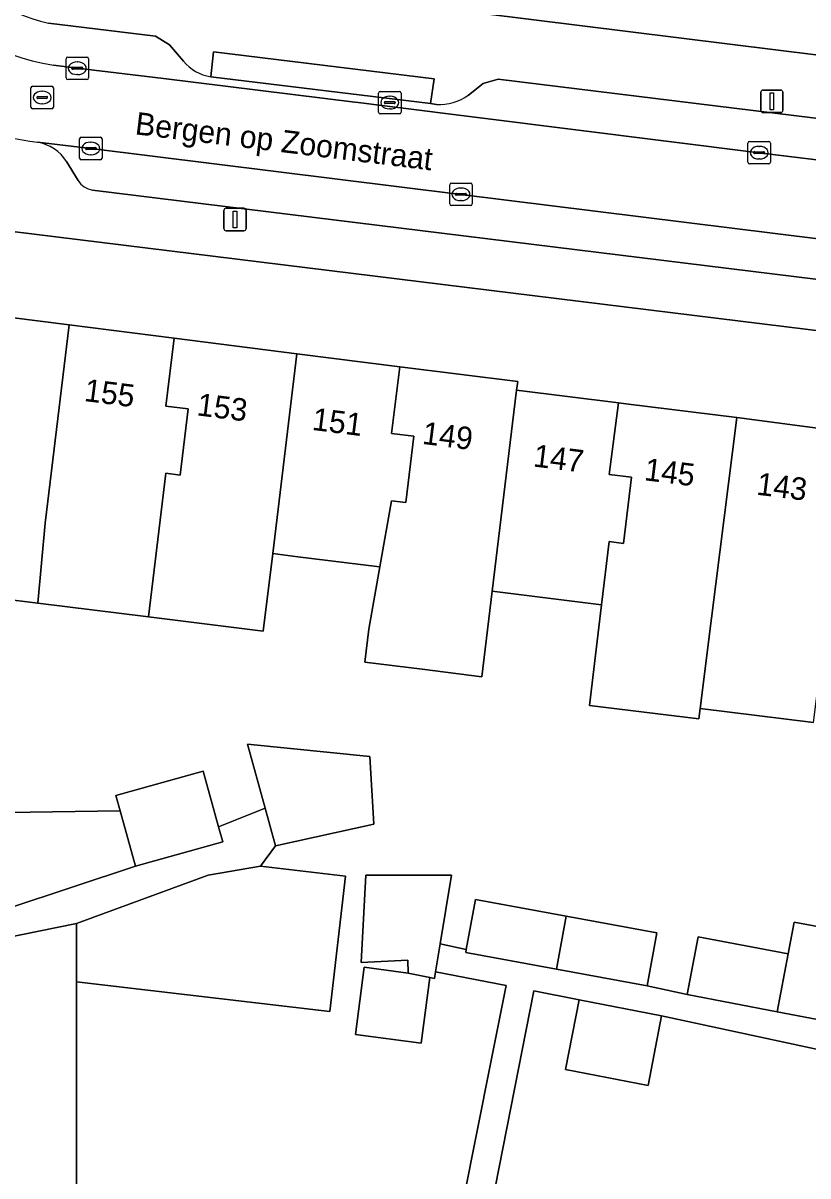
# Model space of a CAD drawing. Extents: x 158086 to 159499, y 382904 to 383981.
# Drawn here: x 158153 to 158187.9, y 383245.1 to 383296.4 of the extents above; entities that cross this region are included whole.
import ezdxf

# ---------------------------------------------------------------- set-up
doc = ezdxf.new("R2010")
doc.units = 0
for name, color, linetype in [('IMGEO_Erf', 7, 'Continuous'), ('IMGEO_Kolk', 7, 'Continuous'), ('IMGEO_Lichtmast', 7, 'Continuous'), ('IMGEO_Openbare_ruimte_label', 7, 'Continuous'), ('IMGEO_Pand', 7, 'Continuous'), ('IMGEO_Pand_nummerreeks', 7, 'Continuous'), ('IMGEO_Parkeervlak_open', 7, 'Continuous'), ('IMGEO_Rijbaan_lokaal_open', 7, 'Continuous'), ('IMGEO_Rioolput', 7, 'Continuous'), ('IMGEO_Voetpad_open', 7, 'Continuous')]:
    doc.layers.add(name, color=color, linetype=linetype)

msp = doc.modelspace()

# ---------------------------------------------------------------- linework, layer by layer
at = {"layer": 'IMGEO_Erf'}
for points in [[(158209.755, 383315.214), (158208.52, 383315.331), (158208.189, 383312.446), (158204.345, 383312.887), (158204.46, 383313.889), (158201.32, 383314.249), (158201.561, 383316.349), (158199.529, 383316.599), (158199.3, 383314.601), (158195.034, 383311.729), (158193.798, 383313.563), (158180.21, 383304.272), (158180.21, 383303.461), (158171.168, 383297.074), (158186.591, 383295.165), (158240.182, 383288.537)], [(158188.163, 383265.252), (158183.107, 383265.876), (158183.05, 383265.426), (158178.18, 383266.016), (158178.722, 383270.493), (158173.853, 383271.094), (158173.391, 383267.293), (158170.741, 383267.624), (158168.187, 383267.943), (158168.371, 383269.412), (158168.857, 383272.174), (158168.719, 383272.191), (158165.209, 383272.63), (158164.088, 383272.77), (158163.663, 383269.323), (158158.563, 383269.952), (158153.625, 383270.561), (158148.582, 383271.182)], [(158152.279, 383261.248), (158157.29, 383261.32), (158157.099, 383262.004), (158160.989, 383263.089), (158161.678, 383260.617), (158163.75, 383261.445), (158162.957, 383264.29), (158168.411, 383263.741), (158168.593, 383260.732), (158164.215, 383259.776), (158163.541, 383258.86), (158167.324, 383258.421), (158166.626, 383252.405), (158155.348, 383253.712), (158155.352, 383242.078)], [(158171.948, 383240.905), (158173.795, 383250.149), (158174.473, 383253.551), (158171.329, 383254.171), (158171.28, 383253.873), (158171.074, 383253.915), (158170.699, 383250.993), (158167.766, 383251.37), (158168.151, 383254.364), (158170.117, 383254.111), (158170.098, 383254.684), (158168.023, 383254.585), (158168.232, 383258.465), (158172.042, 383258.471), (158171.534, 383255.403), (158172.699, 383255.158), (158173.106, 383257.383), (158177.143, 383256.644), (158181.18, 383255.905), (158180.748, 383253.547), (158182.537, 383253.154), (158183.024, 383255.723), (158187.034, 383254.963), (158187.302, 383256.377), (158191.272, 383255.625)], [(158199.077, 383244.67), (158199.655, 383247.658), (158197.155, 383248.138), (158196.461, 383245.085), (158192.336, 383246.023), (158193.03, 383249.076), (158193.162, 383249.657), (158188.003, 383250.786), (158181.398, 383252.206), (158180.792, 383249.102), (158177.118, 383249.82), (158177.725, 383252.924), (158175.714, 383253.312), (158172.957, 383239.361)]]:
    msp.add_lwpolyline(points, dxfattribs=at)
msp.add_lwpolyline([(158145.267, 383287.982), (158144.807, 383284.241), (158149.73, 383283.618), (158155.024, 383282.947), (158159.702, 383282.355), (158165.165, 383281.663), (158169.74, 383281.084), (158174.989, 383280.42), (158174.941, 383280.041), (158179.471, 383279.48), (158179.804, 383279.439), (158184.749, 383278.826), (158189.344, 383278.218), (158189.698, 383278.214), (158194.749, 383277.588), (158199.264, 383277.029), (158199.607, 383276.987), (158204.62, 383276.366), (158205.148, 383280.625)], close=True, dxfattribs=at)
at = {"layer": 'IMGEO_Kolk'}
for p, q in [((158154.961, 383294.861), (158155.813, 383294.861)), ((158154.886, 383293.935), (158154.886, 383294.787)), ((158155.145, 383294.355), (158155.145, 383294.367)), ((158155.188, 383294.404), (158155.586, 383294.404)), ((158155.374, 383294.641), (158155.399, 383294.641)), ((158155.629, 383294.367), (158155.629, 383294.355)), ((158155.887, 383294.787), (158155.887, 383293.935)), ((158155.813, 383293.861), (158154.961, 383293.861)), ((158155.583, 383294.318), (158155.185, 383294.318)), ((158155.397, 383294.081), (158155.372, 383294.081)), ((158168.871, 383293.333), (158169.723, 383293.333)), ((158168.796, 383292.407), (158168.796, 383293.259)), ((158169.055, 383292.827), (158169.055, 383292.839)), ((158169.098, 383292.876), (158169.496, 383292.876)), ((158169.284, 383293.113), (158169.309, 383293.113)), ((158169.539, 383292.839), (158169.539, 383292.827)), ((158169.797, 383293.259), (158169.797, 383292.407)), ((158169.723, 383292.333), (158168.871, 383292.333)), ((158169.493, 383292.79), (158169.095, 383292.79)), ((158169.307, 383292.553), (158169.282, 383292.553)), ((158155.564, 383291.293), (158156.416, 383291.293)), ((158155.489, 383290.367), (158155.489, 383291.219)), ((158155.748, 383290.787), (158155.748, 383290.799)), ((158155.791, 383290.836), (158156.189, 383290.836)), ((158155.977, 383291.073), (158156.002, 383291.073)), ((158156.232, 383290.799), (158156.232, 383290.787)), ((158156.49, 383291.219), (158156.49, 383290.367)), ((158185.239, 383290.18), (158185.239, 383291.032)), ((158185.314, 383291.106), (158186.166, 383291.106)), ((158185.727, 383290.886), (158185.752, 383290.886)), ((158186.24, 383291.032), (158186.24, 383290.18)), ((158156.416, 383290.293), (158155.564, 383290.293)), ((158156.186, 383290.75), (158155.788, 383290.75)), ((158156, 383290.513), (158155.975, 383290.513)), ((158185.498, 383290.6), (158185.498, 383290.612)), ((158185.936, 383290.563), (158185.538, 383290.563)), ((158185.541, 383290.649), (158185.939, 383290.649)), ((158185.75, 383290.326), (158185.725, 383290.326)), ((158185.982, 383290.612), (158185.982, 383290.6)), ((158186.166, 383290.106), (158185.314, 383290.106)), ((158172.04, 383289.251), (158172.892, 383289.251)), ((158171.965, 383288.325), (158171.965, 383289.177)), ((158172.224, 383288.745), (158172.224, 383288.757)), ((158172.662, 383288.708), (158172.264, 383288.708)), ((158172.267, 383288.794), (158172.665, 383288.794)), ((158172.453, 383289.031), (158172.478, 383289.031)), ((158172.708, 383288.757), (158172.708, 383288.745)), ((158172.966, 383289.177), (158172.966, 383288.325)), ((158172.892, 383288.251), (158172.04, 383288.251)), ((158172.476, 383288.471), (158172.451, 383288.471))]:
    msp.add_line(p, q, dxfattribs=at)
for points in [[(158154.961, 383294.861), (158155.813, 383294.861)], [(158154.886, 383293.935), (158154.886, 383294.787)], [(158155.887, 383294.787), (158155.887, 383293.935)], [(158155.813, 383293.861), (158154.961, 383293.861)], [(158168.871, 383293.333), (158169.723, 383293.333)], [(158168.796, 383292.407), (158168.796, 383293.259)], [(158169.797, 383293.259), (158169.797, 383292.407)], [(158169.723, 383292.333), (158168.871, 383292.333)], [(158155.564, 383291.293), (158156.416, 383291.293)], [(158155.489, 383290.367), (158155.489, 383291.219)], [(158156.49, 383291.219), (158156.49, 383290.367)], [(158185.239, 383290.18), (158185.239, 383291.032)], [(158185.314, 383291.106), (158186.166, 383291.106)], [(158186.24, 383291.032), (158186.24, 383290.18)], [(158156.416, 383290.293), (158155.564, 383290.293)], [(158186.166, 383290.106), (158185.314, 383290.106)], [(158172.04, 383289.251), (158172.892, 383289.251)], [(158171.965, 383288.325), (158171.965, 383289.177)], [(158172.966, 383289.177), (158172.966, 383288.325)], [(158172.892, 383288.251), (158172.04, 383288.251)]]:
    msp.add_lwpolyline(points, dxfattribs=at)
for centre, radius, start, end in [((158154.963, 383294.785), 0.0765, 91.552, 178.448), ((158154.963, 383294.785), 0.0765, 91.552, 178.448), ((158155.811, 383294.785), 0.0765, 1.552, 88.448), ((158155.811, 383294.785), 0.0765, 1.552, 88.448), ((158155.185, 383294.364), 0.0403, 85.8775, 175.7526), ((158155.182, 383294.354), 0.0366, 178.938, 274.7102), ((158155.586, 383294.361), 0.043, 264.8664, 352.4533), ((158155.59, 383294.366), 0.0386, 1.7309, 96.639), ((158154.963, 383293.937), 0.0765, 181.552, 268.448), ((158154.963, 383293.937), 0.0765, 181.552, 268.448), ((158155.811, 383293.937), 0.0765, 271.552, 358.448), ((158155.811, 383293.937), 0.0765, 271.552, 358.448), ((158168.873, 383293.257), 0.0765, 91.552, 178.448), ((158168.873, 383293.257), 0.0765, 91.552, 178.448), ((158169.721, 383293.257), 0.0765, 1.552, 88.448), ((158169.721, 383293.257), 0.0765, 1.552, 88.448), ((158169.095, 383292.836), 0.0403, 85.8775, 175.7526), ((158169.092, 383292.826), 0.0366, 178.938, 274.7102), ((158169.496, 383292.833), 0.043, 264.8664, 352.4533), ((158169.5, 383292.838), 0.0386, 1.7309, 96.639), ((158168.873, 383292.409), 0.0765, 181.552, 268.448), ((158168.873, 383292.409), 0.0765, 181.552, 268.448), ((158169.721, 383292.409), 0.0765, 271.552, 358.448), ((158169.721, 383292.409), 0.0765, 271.552, 358.448), ((158155.566, 383291.217), 0.0765, 91.552, 178.448), ((158155.566, 383291.217), 0.0765, 91.552, 178.448), ((158156.414, 383291.217), 0.0765, 1.552, 88.448), ((158156.414, 383291.217), 0.0765, 1.552, 88.448), ((158155.788, 383290.796), 0.0403, 85.8775, 175.7526), ((158155.785, 383290.786), 0.0366, 178.938, 274.7102), ((158156.189, 383290.793), 0.043, 264.8664, 352.4533), ((158156.193, 383290.798), 0.0386, 1.7309, 96.639), ((158185.316, 383291.03), 0.0765, 91.552, 178.448), ((158185.316, 383291.03), 0.0765, 91.552, 178.448), ((158186.164, 383291.03), 0.0765, 1.552, 88.448), ((158186.164, 383291.03), 0.0765, 1.552, 88.448), ((158155.566, 383290.369), 0.0765, 181.552, 268.448), ((158155.566, 383290.369), 0.0765, 181.552, 268.448), ((158156.414, 383290.369), 0.0765, 271.552, 358.448), ((158156.414, 383290.369), 0.0765, 271.552, 358.448), ((158185.538, 383290.609), 0.0403, 85.8775, 175.7526), ((158185.535, 383290.599), 0.0366, 178.938, 274.7102), ((158185.939, 383290.606), 0.043, 264.8664, 352.4533), ((158185.943, 383290.611), 0.0386, 1.7309, 96.639), ((158185.316, 383290.182), 0.0765, 181.552, 268.448), ((158185.316, 383290.182), 0.0765, 181.552, 268.448), ((158186.164, 383290.182), 0.0765, 271.552, 358.448), ((158186.164, 383290.182), 0.0765, 271.552, 358.448), ((158172.042, 383289.175), 0.0765, 91.552, 178.448), ((158172.042, 383289.175), 0.0765, 91.552, 178.448), ((158172.89, 383289.175), 0.0765, 1.552, 88.448), ((158172.89, 383289.175), 0.0765, 1.552, 88.448), ((158172.264, 383288.754), 0.0403, 85.8775, 175.7526), ((158172.261, 383288.744), 0.0366, 178.938, 274.7102), ((158172.665, 383288.751), 0.043, 264.8664, 352.4533), ((158172.669, 383288.756), 0.0386, 1.7309, 96.639), ((158172.042, 383288.327), 0.0765, 181.552, 268.448), ((158172.042, 383288.327), 0.0765, 181.552, 268.448), ((158172.89, 383288.327), 0.0765, 271.552, 358.448), ((158172.89, 383288.327), 0.0765, 271.552, 358.448)]:
    msp.add_arc(centre, radius, start, end, dxfattribs=at)
for centre, major_axis, ratio, start_param, end_param in [((158155.373, 383294.361), (-0.387, 0.002), 0.722429, 4.712389, 7.853982), ((158155.398, 383294.361), (-0.39, 0.002), 0.717154, 1.570796, 4.712389), ((158169.283, 383292.833), (-0.387, 0.002), 0.722429, 4.712389, 7.853982), ((158169.308, 383292.833), (-0.39, 0.002), 0.717154, 1.570796, 4.712389), ((158155.976, 383290.793), (-0.387, 0.002), 0.722429, 4.712389, 7.853982), ((158156.001, 383290.793), (-0.39, 0.002), 0.717154, 1.570796, 4.712389), ((158185.726, 383290.606), (-0.387, 0.002), 0.722429, 4.712389, 7.853982), ((158185.751, 383290.606), (-0.39, 0.002), 0.717154, 1.570796, 4.712389), ((158172.452, 383288.751), (-0.387, 0.002), 0.722429, 4.712389, 7.853982), ((158172.477, 383288.751), (-0.39, 0.002), 0.717154, 1.570796, 4.712389)]:
    msp.add_ellipse(centre, major_axis=major_axis, ratio=ratio, start_param=start_param, end_param=end_param, dxfattribs=at)
at = {"layer": 'IMGEO_Lichtmast'}
for p, q in [((158185.906, 383293.392), (158186.696, 383293.392)), ((158186.696, 383293.392), (158185.906, 383293.392)), ((158185.806, 383292.492), (158185.806, 383293.292)), ((158185.806, 383293.292), (158185.806, 383292.492)), ((158186.796, 383293.292), (158186.796, 383292.492)), ((158186.796, 383292.492), (158186.796, 383293.292)), ((158186.696, 383292.392), (158185.906, 383292.392)), ((158185.906, 383292.392), (158186.696, 383292.392)), ((158161.912, 383287.234), (158161.912, 383288.034)), ((158161.912, 383288.034), (158161.912, 383287.234)), ((158162.012, 383288.134), (158162.802, 383288.134)), ((158162.802, 383288.134), (158162.012, 383288.134)), ((158162.902, 383288.034), (158162.902, 383287.234)), ((158162.902, 383287.234), (158162.902, 383288.034)), ((158162.802, 383287.134), (158162.012, 383287.134)), ((158162.012, 383287.134), (158162.802, 383287.134))]:
    msp.add_line(p, q, dxfattribs=at)
for points in [[(158186.226, 383293.267), (158186.376, 383293.267), (158186.376, 383292.517), (158186.226, 383292.517), (158186.226, 383293.267)], [(158162.332, 383288.009), (158162.482, 383288.009), (158162.482, 383287.259), (158162.332, 383287.259), (158162.332, 383288.009)]]:
    msp.add_lwpolyline(points, dxfattribs=at)
for centre, start, end in [((158185.906, 383293.292), 90, 180), ((158185.906, 383293.292), 90, 180), ((158186.696, 383293.292), 0, 90), ((158186.696, 383293.292), 360, 90), ((158185.906, 383292.492), 180, 270), ((158185.906, 383292.492), 180, 270), ((158186.696, 383292.492), 270, 0), ((158186.696, 383292.492), 270, 0), ((158162.012, 383288.034), 90, 180), ((158162.012, 383288.034), 90, 180), ((158162.802, 383288.034), 0, 90), ((158162.802, 383288.034), 360, 90), ((158162.012, 383287.234), 180, 270), ((158162.012, 383287.234), 180, 270), ((158162.802, 383287.234), 270, 0), ((158162.802, 383287.234), 270, 0)]:
    msp.add_arc(centre, 0.1, start, end, dxfattribs=at)
at = {"layer": 'IMGEO_Pand'}
for points in [[(158149.73, 383283.618), (158149.364, 383280.593), (158150.356, 383280.472), (158150, 383277.528), (158149.36, 383277.606), (158148.582, 383271.182), (158153.625, 383270.561), (158153.955, 383274.12), (158155.024, 383282.947)], [(158158.563, 383269.952), (158159.33, 383276.341), (158159.97, 383276.263), (158160.326, 383279.207), (158159.334, 383279.328), (158159.702, 383282.355), (158155.024, 383282.947), (158153.955, 383274.12), (158153.625, 383270.561)], [(158158.563, 383269.952), (158163.663, 383269.323), (158164.088, 383272.77), (158165.165, 383281.663), (158159.702, 383282.355), (158159.334, 383279.328), (158160.326, 383279.207), (158159.97, 383276.263), (158159.33, 383276.341)], [(158169.74, 383281.084), (158165.165, 383281.663), (158164.088, 383272.77), (158165.209, 383272.63), (158168.719, 383272.191), (158168.857, 383272.174), (158169.376, 383275.124), (158170.016, 383275.046), (158170.372, 383277.99), (158169.38, 383278.111)], [(158174.941, 383280.041), (158174.989, 383280.42), (158169.74, 383281.084), (158169.38, 383278.111), (158170.372, 383277.99), (158170.016, 383275.046), (158169.376, 383275.124), (158168.857, 383272.174), (158168.371, 383269.412), (158168.187, 383267.943), (158170.741, 383267.624), (158173.391, 383267.293), (158173.853, 383271.094)], [(158180.058, 383276.17), (158179.066, 383276.291), (158179.471, 383279.48), (158174.941, 383280.041), (158173.853, 383271.094), (158178.722, 383270.493), (158179.062, 383273.304), (158179.702, 383273.226)], [(158184.749, 383278.826), (158179.804, 383279.439), (158179.471, 383279.48), (158179.066, 383276.291), (158180.058, 383276.17), (158179.702, 383273.226), (158179.062, 383273.304), (158178.722, 383270.493), (158178.18, 383266.016), (158183.05, 383265.426), (158183.107, 383265.876), (158183.616, 383269.89)], [(158189.344, 383278.218), (158184.749, 383278.826), (158183.616, 383269.89), (158183.107, 383265.876), (158188.163, 383265.252), (158188.658, 383269.268), (158188.958, 383272.1), (158189.598, 383272.022), (158189.954, 383274.966), (158188.962, 383275.087)], [(158163.75, 383261.445), (158164.215, 383259.776), (158168.593, 383260.732), (158168.411, 383263.741), (158162.957, 383264.29)], [(158157.29, 383261.32), (158157.976, 383258.86), (158161.866, 383259.944), (158161.678, 383260.617), (158160.989, 383263.089), (158157.099, 383262.004)], [(158157.29, 383261.32), (158152.279, 383261.248), (158152.296, 383260.053), (158152.336, 383257.26), (158152.34, 383256.989), (158157.976, 383258.86)], [(158163.541, 383258.86), (158161.21, 383258.471), (158155.347, 383256.316), (158155.348, 383253.712), (158166.626, 383252.405), (158167.324, 383258.421)], [(158170.117, 383254.111), (158171.074, 383253.915), (158171.28, 383253.873), (158171.329, 383254.171), (158171.534, 383255.403), (158172.042, 383258.471), (158168.232, 383258.465), (158168.023, 383254.585), (158170.098, 383254.684)], [(158177.143, 383256.644), (158173.106, 383257.383), (158172.699, 383255.158), (158172.675, 383255.025), (158176.711, 383254.286)], [(158177.143, 383256.644), (158176.711, 383254.286), (158180.748, 383253.547), (158181.18, 383255.905)], [(158155.348, 383253.712), (158155.347, 383256.316), (158139.526, 383253.098), (158138.355, 383252.86), (158133.459, 383251.844), (158134.686, 383250), (158147.132, 383231.289), (158155.144, 383231.088), (158155.352, 383242.078)], [(158187.034, 383254.963), (158186.545, 383252.387), (158190.516, 383251.635), (158191.272, 383255.625), (158187.302, 383256.377)], [(158186.545, 383252.387), (158187.034, 383254.963), (158183.024, 383255.723), (158182.537, 383253.154)], [(158171.074, 383253.915), (158170.117, 383254.111), (158168.151, 383254.364), (158167.766, 383251.37), (158170.699, 383250.993)], [(158181.398, 383252.206), (158177.725, 383252.924), (158177.118, 383249.82), (158180.792, 383249.102)]]:
    msp.add_lwpolyline(points, close=True, dxfattribs=at)
at = {"layer": 'IMGEO_Parkeervlak_open'}
for points in [[(158160.108, 383294.679), (158159.49, 383295.402), (158158.874, 383295.787), (158154.106, 383296.366)], [(158154.333, 383294.506), (158155.383, 383294.36), (158159.222, 383293.902), (158167.743, 383292.859), (158167.892, 383292.844), (158169.18, 383292.668), (158185.736, 383290.605), (158202.298, 383288.579), (158218.957, 383286.536), (158235.058, 383284.554), (158237.514, 383284.273)], [(158171.375, 383292.756), (158171.114, 383292.788), (158161.332, 383293.987)], [(158196.941, 383291.08), (158174.116, 383293.883), (158173.459, 383293.686), (158172.793, 383293.169)], [(158240.715, 383280.327), (158240.187, 383280.392), (158223.898, 383282.41), (158205.961, 383284.626), (158188.491, 383286.753), (158172.462, 383288.752), (158155.987, 383290.794), (158153.621, 383291.07)], [(158154.91, 383290.208), (158155.419, 383289.361)], [(158156.066, 383288.94), (158222.479, 383280.769)]]:
    msp.add_lwpolyline(points, dxfattribs=at)
msp.add_lwpolyline([(158171.114, 383292.788), (158171.273, 383293.884), (158161.456, 383295.096), (158161.332, 383293.987)], close=True, dxfattribs=at)
for centre, radius, start, end in [((158155.633, 383303.379), 7.177, 211.9681, 257.7181), ((158155.556, 383303.281), 8.86, 212.4449, 262.0642), ((158161.618, 383295.922), 1.956, 219.4493, 261.5866), ((158171.546, 383294.809), 2.06, 265.2363, 307.2407), ((158153.288, 383289.177), 1.922, 32.4321, 80.0238), ((158156.232, 383289.903), 0.977, 213.6803, 260.216)]:
    msp.add_arc(centre, radius, start, end, dxfattribs=at)
at = {"layer": 'IMGEO_Rijbaan_lokaal_open'}
for points in [[(158185.736, 383290.605), (158169.18, 383292.668), (158167.892, 383292.844), (158167.743, 383292.859), (158159.222, 383293.902), (158155.383, 383294.36), (158154.333, 383294.506)], [(158153.621, 383291.07), (158155.987, 383290.794), (158172.462, 383288.752), (158188.491, 383286.753), (158205.961, 383284.626), (158223.898, 383282.41), (158240.187, 383280.392), (158240.512, 383283.921), (158237.514, 383284.273), (158235.058, 383284.554), (158218.957, 383286.536), (158202.298, 383288.579), (158185.736, 383290.605)]]:
    msp.add_lwpolyline(points, dxfattribs=at)
for centre, radius, start, end in [((158155.556, 383303.281), 8.86, 212.4449, 262.0642), ((158154.707, 383300.876), 9.866, 231.7789, 263.6804)]:
    msp.add_arc(centre, radius, start, end, dxfattribs=at)
at = {"layer": 'IMGEO_Rioolput'}
for p, q in [((158153.325, 383292.634), (158153.325, 383293.486)), ((158153.4, 383293.56), (158154.252, 383293.56)), ((158153.813, 383293.34), (158153.838, 383293.34)), ((158154.326, 383293.486), (158154.326, 383292.634)), ((158153.584, 383293.054), (158153.584, 383293.066)), ((158154.022, 383293.017), (158153.624, 383293.017)), ((158153.627, 383293.103), (158154.025, 383293.103)), ((158154.068, 383293.066), (158154.068, 383293.054)), ((158154.252, 383292.56), (158153.4, 383292.56)), ((158153.836, 383292.78), (158153.811, 383292.78))]:
    msp.add_line(p, q, dxfattribs=at)
for points in [[(158153.325, 383292.634), (158153.325, 383293.486)], [(158153.4, 383293.56), (158154.252, 383293.56)], [(158154.326, 383293.486), (158154.326, 383292.634)], [(158154.252, 383292.56), (158153.4, 383292.56)]]:
    msp.add_lwpolyline(points, dxfattribs=at)
for centre, radius, start, end in [((158153.402, 383293.484), 0.0765, 91.552, 178.448), ((158153.402, 383293.484), 0.0765, 91.552, 178.448), ((158154.25, 383293.484), 0.0765, 1.552, 88.448), ((158154.25, 383293.484), 0.0765, 1.552, 88.448), ((158153.624, 383293.063), 0.0403, 85.8775, 175.7526), ((158153.621, 383293.053), 0.0366, 178.938, 274.7102), ((158154.025, 383293.06), 0.043, 264.8664, 352.4533), ((158154.029, 383293.065), 0.0386, 1.7309, 96.639), ((158153.402, 383292.636), 0.0765, 181.552, 268.448), ((158153.402, 383292.636), 0.0765, 181.552, 268.448), ((158154.25, 383292.636), 0.0765, 271.552, 358.448), ((158154.25, 383292.636), 0.0765, 271.552, 358.448)]:
    msp.add_arc(centre, radius, start, end, dxfattribs=at)
for centre, major_axis, ratio, start_param, end_param in [((158153.812, 383293.06), (-0.387, 0.002), 0.722429, 4.712389, 7.853982), ((158153.837, 383293.06), (-0.39, 0.002), 0.717154, 1.570796, 4.712389)]:
    msp.add_ellipse(centre, major_axis=major_axis, ratio=ratio, start_param=start_param, end_param=end_param, dxfattribs=at)
at = {"layer": 'IMGEO_Voetpad_open'}
for points in [[(158186.591, 383295.165), (158171.168, 383297.074), (158165.494, 383297.776), (158165.111, 383297.823), (158159.76, 383298.486), (158159.181, 383298.556), (158157.959, 383298.704), (158157.933, 383298.551), (158156.713, 383298.704), (158156.713, 383298.547), (158155.846, 383298.637), (158155.809, 383298.506), (158152.564, 383298.893), (158147.784, 383305.841), (158145.745, 383308.83), (158143.174, 383307.068)], [(158137.608, 383300.368), (158142.58, 383293.054), (158144.553, 383290.136), (158143.898, 383289.306), (158143.758, 383288.167), (158145.267, 383287.982), (158205.148, 383280.625), (158206.097, 383280.508), (158207.45, 383280.342), (158274.982, 383272.062), (158277.718, 383271.726), (158339.394, 383264.164)], [(158154.106, 383296.366), (158158.874, 383295.787), (158159.49, 383295.402), (158160.108, 383294.679)], [(158161.332, 383293.987), (158161.456, 383295.096), (158171.273, 383293.884), (158171.114, 383292.788), (158171.375, 383292.756)], [(158245.147, 383288.036), (158240.303, 383288.508), (158240.182, 383288.537), (158186.591, 383295.165)], [(158172.793, 383293.169), (158173.459, 383293.686), (158174.116, 383293.883), (158196.941, 383291.08)], [(158155.419, 383289.361), (158154.91, 383290.208)], [(158222.479, 383280.769), (158156.066, 383288.94)], [(158190.516, 383251.635), (158186.545, 383252.387), (158182.537, 383253.154), (158180.748, 383253.547), (158176.711, 383254.286), (158172.675, 383255.025), (158172.699, 383255.158), (158171.534, 383255.403), (158171.329, 383254.171), (158174.473, 383253.551), (158173.795, 383250.149), (158171.948, 383240.905)], [(158172.957, 383239.361), (158175.714, 383253.312), (158177.725, 383252.924), (158181.398, 383252.206), (158188.003, 383250.786), (158193.162, 383249.657), (158193.03, 383249.076), (158197.155, 383248.138), (158199.655, 383247.658), (158204.221, 383246.774), (158210.732, 383246.125)]]:
    msp.add_lwpolyline(points, dxfattribs=at)
msp.add_lwpolyline([(158144.807, 383284.241), (158145.267, 383287.982), (158143.758, 383288.167), (158143.258, 383284.106), (158141.208, 383267.072), (158139.526, 383253.098), (158155.347, 383256.316), (158161.21, 383258.471), (158163.541, 383258.86), (158164.215, 383259.776), (158163.75, 383261.445), (158161.678, 383260.617), (158161.866, 383259.944), (158157.976, 383258.86), (158152.34, 383256.989), (158152.336, 383257.26), (158149.581, 383257.103), (158149.622, 383256.39), (158146.52, 383255.8), (158141.296, 383254.807), (158142.091, 383261.864), (158143.705, 383275.309), (158144.195, 383279.279)], close=True, dxfattribs=at)
for centre, radius, start, end in [((158155.633, 383303.379), 7.177, 211.9681, 257.7181), ((158161.618, 383295.922), 1.956, 219.4493, 261.5866), ((158154.707, 383300.876), 9.866, 231.7789, 263.6804), ((158171.546, 383294.809), 2.06, 265.2363, 307.2407), ((158153.288, 383289.177), 1.922, 32.4321, 80.0238), ((158156.232, 383289.903), 0.977, 213.6803, 260.216)]:
    msp.add_arc(centre, radius, start, end, dxfattribs=at)

# ---------------------------------------------------------------- texts
at = {"layer": 'IMGEO_Openbare_ruimte_label'}
msp.add_text('Bergen op Zoomstraat', height=1, rotation=353.0526, dxfattribs=at).set_placement((158157.926, 383291.427))
at = {"layer": 'IMGEO_Pand_nummerreeks'}
for s, rotation, p in [('155', 352.7839, (158155.66, 383279.56)), ('153', 352.7839, (158160.676, 383278.925)), ('151', 352.7865, (158165.805, 383278.276)), ('149', 352.7865, (158170.708, 383277.655)), ('147', 352.9412, (158175.649, 383276.648)), ('145', 352.9412, (158180.595, 383276.036)), ('143', 352.9412, (158185.588, 383275.395))]:
    msp.add_text(s, height=1, rotation=rotation, dxfattribs=at).set_placement(p)

doc.saveas('drawing.dxf')
